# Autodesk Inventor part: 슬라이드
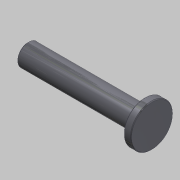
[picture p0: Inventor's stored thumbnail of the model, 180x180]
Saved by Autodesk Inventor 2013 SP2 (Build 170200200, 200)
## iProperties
Created: 2015-10
Part Number: 슬라이드
Document SubType Name: Modeling
Designer: mdu
Density: 1 g/cm^3
Material: 강철, 연강
Author: mdu
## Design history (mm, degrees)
sketch "스케치1"
  geometry: L1 (-75, 162)-(-75, 58) reference; L2 (-148, 110)-(22, 110); L3 (-148, 110)-(-148, 125); L4 (-148, 125)-(12, 125); L5 (12, 125)-(12, 139); L6 (12, 139)-(22, 139); L7 (22, 139)-(22, 110); 2 further points
  constraints: 12 end point, 3 parallel, 3 perpendicular, 1 midpoint, 1 point on line
  dimensions: "d0" = 58 diameter of L6 L2; "d1" = 30 diameter of L4 L2; "d2" = 10 distance of L5.end L6.end; "d3" = 170 distance of L2.start L2.end; "d4" = 73 distance between parallel lines of L3 L1
revolve "회전1" sketch "스케치1" stored, may be unused: angle "d5" = 90 deg
hole "구멍1" diameter "d11" = 13.376; stored, may be unused: countersink angle "d15" = 90 deg, drill point angle "d17" = 118 deg; dims "d9" = 10, "d10" = 10, "d12" = 22, "d13" = 4, "d14" = 2, "d16" = 25
chamfer "모따기1" distance "d6" = 1; stored, may be unused: second distance "d7" = 2, angle "d8" = 45 deg
node "솔리드1"
node "참조1"
